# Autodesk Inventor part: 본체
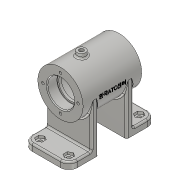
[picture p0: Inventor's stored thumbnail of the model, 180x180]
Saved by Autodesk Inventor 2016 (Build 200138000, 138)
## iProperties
Created: 2017-02
Part Number: 본체
Material: 알루미늄 6061
Document SubType Name: Modeling
Designer: H
Density: 2.7 g/cm^3
Appearance: 알루미늄 - 평지
Mass: 354.768 g
Surface Area: 422.781 cm^2
Volume: 131.396 cm^3
Author: H
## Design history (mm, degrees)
sketch "스케치1"
  geometry: L1 (-52, 27)-(52, 27); L2 (52, 27)-(52, -27); L3 (52, -27)-(-52, -27); L4 (-52, -27)-(-52, 27); L5 (-52, 27)-(52, -27); L6 (52, 27)-(-52, -27); 1 further point
  constraints: 12 end point, 2 midpoint, 2 parallel, 1 horizontal, 1 perpendicular
  dimensions: "d0" = 104 distance of L2.end L3.end; "d1" = 54 distance of L1.end L2.end
extrude "돌출1" new body sketch "스케치1" distance "d2" = 8; taper "d3" = 0 deg
sketch "스케치2"
  geometry: L1 (0, 0)-(0, 8) reference; L2 (0, 8)-(104, 8) reference; L3 (104, 8)-(104, 0) reference; L4 (104, 0)-(0, 0) reference; L5 (35, 0)-(69, 0); L6 (69, 0)-(69, 8); L7 (69, 8)-(35, 8); L8 (35, 8)-(35, 0); 2 further points
  constraints: 8 end point, 2 midpoint, 2 parallel, 2 point on line, 1 horizontal, 1 perpendicular
  dimensions: "d4" = 17 distance from line of L8 point (52, 0)
extrude "돌출2" cut sketch "스케치2" stored distance "d5" = 8; taper "d6" = 0 deg
sketch "스케치3"
  geometry: L1 (-17, 8)-(-17, 0) reference; L2 (-17, 0)-(-52, 0) reference; L3 (-52, 0)-(-52, 8) reference; L4 (-52, 8)-(-17, 8) reference; L5 (52, 0)-(17, 0) reference; L6 (17, 0)-(17, 8) reference; L7 (17, 8)-(52, 8) reference; L8 (52, 8)-(52, 0) reference; L9 (-35, 60)-(35, 60); L10 (-35, 60)-(35, 60); L11 (35, 60)-(35, 87); L12 (35, 87)-(-35, 87); L13 (-35, 87)-(-35, 60); L14 (-17, 8)-(-25, 8); L15 (-25, 8)-(-25, 60); L16 (-25, 60)-(-17, 60); L17 (-17, 60)-(-17, 8); L18 (17, 8)-(25, 8); L19 (25, 8)-(25, 60); L20 (25, 60)-(17, 60); L21 (17, 60)-(17, 8); L22 (-10, 80.673)-(-5, 80.673); L23 (-5, 80.673)-(-5, 92); L24 (-5, 92)-(-10, 92); L25 (-10, 92)-(-10, 80.673); 2 further points
  constraints: 34 end point, 8 parallel, 5 horizontal, 4 perpendicular, 2 collinear, 1 midpoint, 1 vertical alignment
  dimensions: "d7" = 60 distance between parallel lines of L2 L9; "d8" = 70 distance of L9.start L9.end; "d9" = 54 diameter of L12 L9; "d10" = 8 distance of L15.end L16.end; "d11" = 8 distance of L20.end L19.end; "d12" = 25 distance between parallel lines of L13 L25; "d13" = 5 distance between parallel lines of L12 L24; "d14" = 10 diameter of L23 L25; "d15" = 11.32659 distance of L22.end L23.end
  node "절단 모서리 투영2"
revolve "회전1" stored, may be unused: angle "d16" = 90 deg
extrude "돌출3" join sketch "스케치3" stored distance "d17" = 54; taper "d18" = 0 deg
revolve "회전2" stored, may be unused: angle "d19" = 90 deg
fillet "모깎기1" dims "d20" = 10
node "작업 평면1"
sketch "스케치4"
  geometry: L1 (-18, 87)-(52, 87) reference; L2 (-18, 33)-(-18, 87) reference; 2 further points
  constraints: 1 other
  dimensions: "d22" = 27 distance from line of L1 point (17, 60); "d23" = 35 distance from line of point (17, 60) L2
feature "엠보싱1" sketch "스케치4" dims "d0" = 104, "d1" = 54, "d24" = 0.5, "d25" = 0
sketch "스케치5"
  geometry: L1 (61.941, 27.431)-(61.906, 26.933) reference; L2 (61.576, 26.954)-(61.605, 27.453) reference; L3 (60, 0)-(33, 0); L4 (60, 0)-(34.84, -16.339); L5 (34.84, -16.339)-(38.108, -21.371); L6 (38.108, -21.371)-(63.268, -5.032); L7 (63.268, -5.032)-(60, 0); A1 r 27.5 centre (60, 0) between (61.941, 27.431) and (61.605, 27.453) reference; A2 r 27 centre (60, 0) between (61.576, 26.954) and (61.906, 26.933) reference; 1 further point
  constraints: 10 end point, 2 parallel, 1 horizontal, 1 perpendicular, 1 point on circle
  dimensions: "d26" = 30 distance of L5.end L6.end; "d27" = 33 deg angle of L3 L4; "d28" = 12 diameter of L6 L4
revolve "회전3" sketch "스케치5" stored, may be unused: angle "d29" = 90 deg
sketch "스케치6"
  geometry: L1 (-35, 33)-(-35, 87) reference; L2 (35, 33)-(35, 87) reference; L3 (-35, 60)-(35, 60); L4 (-42, 0)-(-17, 0) reference; L5 (-35, 60)-(-23, 60); L6 (-23, 60)-(-23, 76); L7 (-23, 76)-(-35, 76); L8 (-35, 76)-(-35, 60); L9 (-23, 60)-(-20, 60); L10 (-20, 60)-(-20, 74); L11 (-20, 74)-(-23, 74); L12 (-23, 74)-(-23, 60); L13 (-20, 60)-(20, 60); L14 (20, 60)-(20, 82); L15 (20, 82)-(-20, 82); L16 (-20, 82)-(-20, 60); L17 (20, 60)-(23, 60); L18 (23, 60)-(23, 74); L19 (23, 74)-(20, 74); L20 (20, 74)-(20, 60); L21 (23, 60)-(35, 60); L22 (35, 60)-(35, 76); L23 (35, 76)-(23, 76); L24 (23, 76)-(23, 60); 2 further points
  constraints: 42 end point, 10 parallel, 6 horizontal, 5 perpendicular, 1 midpoint, 1 point on line, 1 vertical alignment
  dimensions: "d30" = 70 distance of L3.start L3.end; "d31" = 60 distance between parallel lines of L4 L3; "d32" = 32 diameter of L7 L3; "d33" = 28 diameter of L11 L3; "d34" = 44 diameter of L15 L3; "d35" = 28 diameter of L19 L3; "d36" = 32 diameter of L23 L3; "d37" = 12 distance of L6.end L7.end; "d38" = 3 distance between parallel lines of L10 L12; "d39" = 40 distance of L14.end L15.end; "d40" = 3 distance of L18.end L19.end
revolve "회전4" sketch "스케치6" stored, may be unused: angle "d41" = 90 deg
sketch "스케치7"
  geometry: C1 r 5 at (0, 0) reference; 1 further point
hole "구멍1" sketch "스케치7" at (0, 0) diameter "d42" = 5.188; stored, may be unused: countersink angle "d46" = 90 deg, drill point angle "d48" = 118 deg; dims "d43" = 12, "d44" = 4, "d45" = 2, "d47" = 20
sketch "스케치8"
  geometry: C1 r 6 at (0, 0) reference; 1 further point
hole "구멍2" sketch "스케치8" at (0, 0) diameter "d49" = 5.188; stored, may be unused: countersink angle "d53" = 90 deg, drill point angle "d55" = 118 deg; dims "d50" = 12, "d51" = 4, "d52" = 2, "d54" = 20
fillet "모깎기2" dims "d56" = 2
fillet "모깎기3" dims "d57" = 2
fillet "모깎기4" dims "d58" = 2
fillet "모깎기5" dims "d59" = 3
chamfer "모따기1" distance "d60" = 1; stored, may be unused: second distance "d61" = 2, angle "d62" = 45 deg
sketch "스케치9" dims "d63" = 42
  geometry: C1 r 27 at (0, 0) reference; C2 r 17 at (0, 0) reference; 3 further points
  constraints: 2 vertical alignment, 1 coincident, 2 other
hole "구멍3" sketch "스케치9" at (0, 21) diameter "d64" = 3.242; stored, may be unused: countersink angle "d68" = 90 deg, drill point angle "d70" = 118 deg; dims "d65" = 8, "d66" = 4, "d67" = 2, "d69" = 10
node "작업 평면2"
sketch "스케치10" dims "d74" = 9, "d75" = 9, "d76" = 9, "d77" = 9
  geometry: L1 (-19, -27)-(-23.536, -27) reference; L2 (-42, -25)-(-27, -25) reference; L3 (-50, 17)-(-50, -17) reference; L4 (-27, 25)-(-42, 25) reference; L5 (-27, 25)-(-27, -25) reference; L6 (-17, 25)-(-17, -25) reference; L7 (-23.536, 27)-(-19, 27) reference; L8 (42, 25)-(27, 25) reference; L9 (50, -17)-(50, 17) reference; L10 (27, -25)-(42, -25) reference; L11 (27, -25)-(27, 25) reference; L12 (19, 27)-(23.536, 27) reference; L13 (17, -25)-(17, 25) reference; L14 (23.536, -27)-(19, -27) reference; L15 (-39.402, -12.5)-(-36.804, -17); L16 (-36.804, -17)-(-39.402, -21.5); L17 (-39.402, -21.5)-(-44.598, -21.5); L18 (-44.598, -21.5)-(-47.196, -17); L19 (-47.196, -17)-(-44.598, -12.5); L20 (-44.598, -12.5)-(-39.402, -12.5); L21 (-42, -17)-(-42, -12.5); L22 (-36.804, 17)-(-39.402, 12.5); L23 (-39.402, 12.5)-(-44.598, 12.5); L24 (-42, 17)-(-42, 21.5); L25 (-44.598, 21.5)-(-39.402, 21.5); L26 (-44.598, 12.5)-(-47.196, 17); L27 (-47.196, 17)-(-44.598, 21.5); L28 (-39.402, 21.5)-(-36.804, 17); L29 (47.196, 17)-(44.598, 12.5); L30 (44.598, 12.5)-(39.402, 12.5); L31 (42, 17)-(42, 21.5); L32 (39.402, 21.5)-(44.598, 21.5); L33 (39.402, 12.5)-(36.804, 17); L34 (36.804, 17)-(39.402, 21.5); L35 (44.598, 21.5)-(47.196, 17); L36 (47.196, -17)-(44.598, -21.5); L37 (44.598, -21.5)-(39.402, -21.5); L38 (42, -17)-(42, -12.5); L39 (39.402, -12.5)-(44.598, -12.5); L40 (39.402, -21.5)-(36.804, -17); L41 (36.804, -17)-(39.402, -12.5); L42 (44.598, -12.5)-(47.196, -17); A1 r 2 centre (-19, -25) between (-19, -27) and (-17, -25) reference; A2 r 8 centre (-42, -17) between (-50, -17) and (-42, -25) reference; A3 r 8 centre (-42, 17) between (-42, 25) and (-50, 17) reference; A4 r 2 centre (-19, 25) between (-17, 25) and (-19, 27) reference; A5 r 8 centre (42, 17) between (50, 17) and (42, 25) reference; A6 r 8 centre (42, -17) between (42, -25) and (50, -17) reference; A7 r 2 centre (19, 25) between (19, 27) and (17, 25) reference; A8 r 2 centre (19, -25) between (17, -25) and (19, -27) reference; 5 further points
  constraints: 56 end point, 5 coincident, 4 midpoint, 4 vertical, 4 vertical alignment, 64 other
extrude "돌출4" cut sketch "스케치10" distance "d78" = 3; taper "d79" = 0 deg
sketch "스케치11"
  geometry: L1 (44.598, 21.5)-(39.402, 21.5) reference; L2 (39.402, 21.5)-(36.804, 17) reference; L3 (36.804, 17)-(39.402, 12.5) reference; L4 (39.402, 12.5)-(44.598, 12.5) reference; L5 (44.598, 12.5)-(47.196, 17) reference; L6 (47.196, 17)-(44.598, 21.5) reference; L7 (-39.402, -12.5)-(-44.598, -12.5) reference; L8 (-44.598, -12.5)-(-47.196, -17) reference; L9 (-47.196, -17)-(-44.598, -21.5) reference; L10 (-44.598, -21.5)-(-39.402, -21.5) reference; L11 (-39.402, -21.5)-(-36.804, -17) reference; L12 (-36.804, -17)-(-39.402, -12.5) reference; L13 (-39.402, 21.5)-(-44.598, 21.5) reference; L14 (-44.598, 21.5)-(-47.196, 17) reference; L15 (-47.196, 17)-(-44.598, 12.5) reference; L16 (-44.598, 12.5)-(-39.402, 12.5) reference; L17 (-39.402, 12.5)-(-36.804, 17) reference; L18 (-36.804, 17)-(-39.402, 21.5) reference; L19 (44.598, -12.5)-(39.402, -12.5) reference; L20 (39.402, -12.5)-(36.804, -17) reference; L21 (36.804, -17)-(39.402, -21.5) reference; L22 (39.402, -21.5)-(44.598, -21.5) reference; L23 (44.598, -21.5)-(47.196, -17) reference; L24 (47.196, -17)-(44.598, -12.5) reference; L25 (52, 17)-(52, -17) reference; L26 (42, -27)-(19, -27) reference; L27 (17, -25)-(17, 25) reference; L28 (19, 27)-(42, 27) reference; L29 (-42, 27)-(-19, 27) reference; L30 (-17, 25)-(-17, -25) reference; L31 (-19, -27)-(-42, -27) reference; L32 (-52, -17)-(-52, 17) reference; C1 r 2.5 at (-42, -17); C2 r 2.5 at (-42, 17); C3 r 2.5 at (42, 17); C4 r 2.5 at (42, -17); A1 r 10 centre (42, 17) between (52, 17) and (42, 27) reference; A2 r 10 centre (42, -17) between (42, -27) and (52, -17) reference; A3 r 2 centre (19, -25) between (17, -25) and (19, -27) reference; A4 r 2 centre (19, 25) between (19, 27) and (17, 25) reference; A5 r 10 centre (-42, 17) between (-42, 27) and (-52, 17) reference; A6 r 2 centre (-19, 25) between (-17, 25) and (-19, 27) reference; A7 r 2 centre (-19, -25) between (-19, -27) and (-17, -25) reference; A8 r 10 centre (-42, -17) between (-52, -17) and (-42, -27) reference; 1 further point
  constraints: 4 centre point, 1 coincident
  dimensions: "d80" = 5 diameter of C1; "d81" = 5 diameter of C2; "d82" = 5 diameter of C3; "d83" = 5 diameter of C4
extrude "돌출5" cut sketch "스케치11" distance "d84" = 5; taper "d85" = 0 deg
fillet "모깎기6" dims "d86" = 2
fillet "모깎기7" dims "d87" = 0.3
node "솔리드1"
pattern_circular "원형 패턴1" dims angle "d72" = 360 deg
mirror "대칭1"
node "투영된 루프1"
node "투영된 루프2"
node "투영된 루프3"
node "절단 모서리 투영1"
node "절단 모서리 투영3"
node "절단 모서리 투영4"
node "절단 모서리 투영5"
other parameters: "d21" = 25
